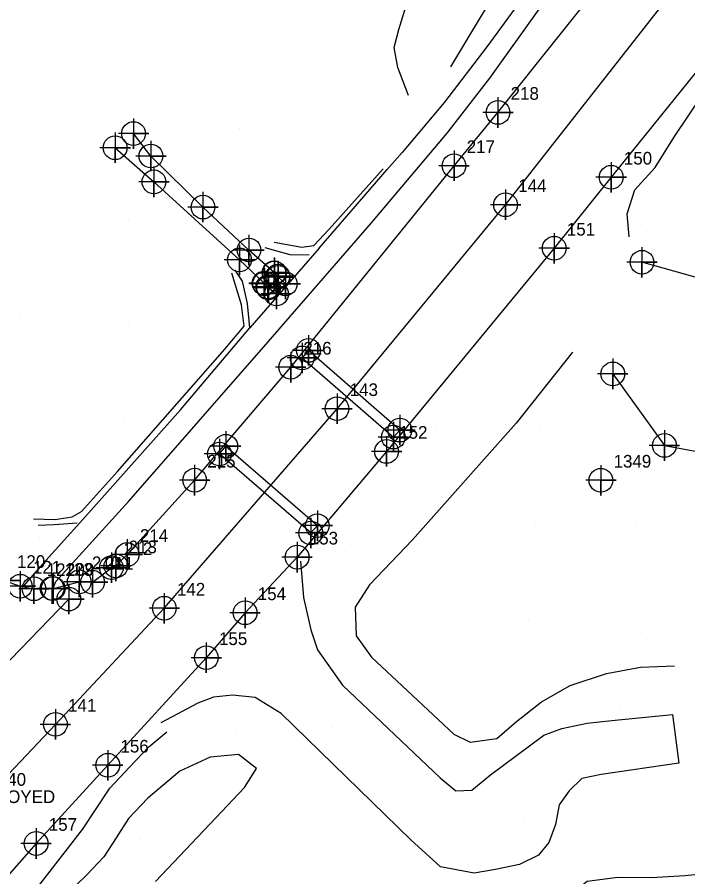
# Model space of a CAD drawing. Extents: x 1497074 to 1501343, y 481943 to 486114.
# Drawn here: x 1498585.8 to 1498718.1, y 484795.7 to 484965.4 of the extents above; entities that cross this region are included whole.
import ezdxf

# ---------------------------------------------------------------- set-up
doc = ezdxf.new("R2010")
doc.units = 0
for name, color, linetype in [('Default Symbol Cogo Comment', 7, 'Continuous'), ('Exist DTM Breakline', 7, 'Continuous'), ('Exist DTM Breakline Cogo Point CELL', 7, 'Continuous'), ('Exist DTM Crownline', 7, 'Continuous'), ('Exist DTM Crownline Cogo Number', 7, 'Continuous'), ('Exist DTM Crownline Cogo Point CELL', 7, 'Continuous'), ('Exist DTM Regular Point CELL', 7, 'Continuous'), ('Exist DTM Regular Point Cogo Number', 7, 'Continuous'), ('Exist Roads EOP', 7, 'Continuous'), ('Exist Roads EOP Cogo Number', 7, 'Continuous'), ('Exist Roads EOP Cogo Point CELL', 7, 'Continuous'), ('Exist Roads EOP Other', 7, 'Continuous'), ('Exist Roads EOP Other Cogo Point CELL', 7, 'Continuous'), ('PH Exist DTM Breakline', 7, 'Continuous'), ('PH Exist DTM Point', 7, 'Continuous'), ('Scratch_Level_8', 7, 'Continuous')]:
    doc.layers.add(name, color=color, linetype=linetype)

msp = doc.modelspace()

# ---------------------------------------------------------------- linework, layer by layer
at = {"layer": 'Exist DTM Breakline'}
for points in [[(1498808.2, 484833.18), (1498802.07, 484856.65), (1498795.16, 484873.78), (1498778.55, 484891.85), (1498758.28, 484902.66), (1498731.74, 484910.66), (1498709.09, 484916.99)], [(1498703.32, 484894.97), (1498713.52, 484880.84), (1498750.48, 484874.03), (1498781.67, 484873.31), (1498801.86, 484846.92)], [(1498566.89, 484820.13), (1498582.51, 484836.65), (1498595.96, 484850.53)]]:
    msp.add_lwpolyline(points, dxfattribs=at)
at = {"layer": 'Exist DTM Breakline Cogo Point CELL'}
for points in [[(1498709.09, 484919.99), (1498709.09, 484913.99), (1498709.09, 484916.99), (1498712.09, 484916.99), (1498706.09, 484916.99)], [(1498643.25, 484902.6), (1498643.25, 484896.6), (1498643.25, 484899.6), (1498646.25, 484899.6), (1498640.25, 484899.6)], [(1498642.03, 484901.11), (1498642.03, 484895.11), (1498642.03, 484898.11), (1498645.03, 484898.11), (1498639.03, 484898.11)], [(1498703.32, 484897.97), (1498703.32, 484891.97), (1498703.32, 484894.97), (1498706.32, 484894.97), (1498700.32, 484894.97)], [(1498661.31, 484886.87), (1498661.31, 484880.87), (1498661.31, 484883.87), (1498664.31, 484883.87), (1498658.31, 484883.87)], [(1498660.01, 484885.5), (1498660.01, 484879.5), (1498660.01, 484882.5), (1498663.01, 484882.5), (1498657.01, 484882.5)], [(1498626.94, 484883.68), (1498626.94, 484877.68), (1498626.94, 484880.68), (1498629.94, 484880.68), (1498623.94, 484880.68)], [(1498713.52, 484883.84), (1498713.52, 484877.84), (1498713.52, 484880.84), (1498716.52, 484880.84), (1498710.52, 484880.84)], [(1498625.69, 484882.16), (1498625.69, 484876.16), (1498625.69, 484879.16), (1498628.69, 484879.16), (1498622.69, 484879.16)], [(1498645.01, 484868.02), (1498645.01, 484862.02), (1498645.01, 484865.02), (1498648.01, 484865.02), (1498642.01, 484865.02)], [(1498643.72, 484866.57), (1498643.72, 484860.57), (1498643.72, 484863.57), (1498646.72, 484863.57), (1498640.72, 484863.57)], [(1498595.96, 484853.53), (1498595.96, 484847.53), (1498595.96, 484850.53), (1498598.96, 484850.53), (1498592.96, 484850.53)]]:
    msp.add_lwpolyline(points, dxfattribs=at)
for centre in [(1498709.09, 484916.99), (1498643.25, 484899.6), (1498642.03, 484898.11), (1498703.32, 484894.97), (1498660.01, 484882.5), (1498661.31, 484883.87), (1498626.94, 484880.68), (1498713.52, 484880.84), (1498625.69, 484879.16), (1498645.01, 484865.02), (1498643.72, 484863.57), (1498595.96, 484850.53)]:
    msp.add_circle(centre, 2.34, dxfattribs=at)
at = {"layer": 'Exist DTM Crownline'}
msp.add_lwpolyline([(1498174.51, 484418.76), (1498211.76, 484454.63), (1498248.88, 484490.3), (1498287.28, 484525.89), (1498324.11, 484560.63), (1498360.29, 484595.61), (1498397.16, 484630.83), (1498419.58, 484652.79), (1498435.06, 484667.86), (1498471.56, 484703.24), (1498507.82, 484739.07), (1498544.95, 484775.1), (1498579.44, 484811.19), (1498593.31, 484825.81), (1498614.8, 484848.72), (1498648.9, 484888.1), (1498682.16, 484928.34), (1498714.31, 484969.37), (1498734.43, 484994.62)], dxfattribs=at)
at = {"layer": 'Exist DTM Crownline Cogo Point CELL'}
for points in [[(1498682.16, 484931.34), (1498682.16, 484925.34), (1498682.16, 484928.34), (1498685.16, 484928.34), (1498679.16, 484928.34)], [(1498648.9, 484891.1), (1498648.9, 484885.1), (1498648.9, 484888.1), (1498651.9, 484888.1), (1498645.9, 484888.1)], [(1498614.8, 484851.72), (1498614.8, 484845.72), (1498614.8, 484848.72), (1498617.8, 484848.72), (1498611.8, 484848.72)], [(1498593.31, 484828.81), (1498593.31, 484822.81), (1498593.31, 484825.81), (1498596.31, 484825.81), (1498590.31, 484825.81)]]:
    msp.add_lwpolyline(points, dxfattribs=at)
for centre in [(1498682.16, 484928.34), (1498648.9, 484888.1), (1498614.8, 484848.72), (1498593.31, 484825.81)]:
    msp.add_circle(centre, 2.34, dxfattribs=at)
at = {"layer": 'Exist DTM Regular Point CELL'}
msp.add_lwpolyline([(1498700.98, 484876.97), (1498700.98, 484870.97), (1498700.98, 484873.97), (1498703.98, 484873.97), (1498697.98, 484873.97)], dxfattribs=at)
msp.add_circle((1498700.98, 484873.97), 2.34, dxfattribs=at)
at = {"layer": 'Exist Roads EOP'}
for points in [[(1498743.66, 484987.16), (1498738.5, 484978.99), (1498725.1, 484961.13), (1498703.01, 484933.77), (1498691.76, 484919.76), (1498658.67, 484879.66), (1498641.02, 484858.8), (1498630.75, 484847.82), (1498623.1, 484838.96), (1498603.65, 484817.74), (1498589.5, 484802.3), (1498575.55, 484786.5), (1498555.48, 484765.72), (1498538.21, 484747.04), (1498518.63, 484726.67), (1498501.9, 484709.28), (1498485.08, 484691.46), (1498474.43, 484677.64), (1498470.63, 484672.31)], [(1498592.65, 484852.62), (1498592.89, 484852.61), (1498598.02, 484853.93), (1498600.65, 484853.85), (1498604.36, 484856.72), (1498605.26, 484857.06), (1498607.49, 484859.32), (1498620.79, 484873.99), (1498639.75, 484896.28), (1498671.99, 484936.03), (1498680.66, 484946.55), (1498705.53, 484977.75)], [(1498496.38, 484929.75), (1498503.37, 484923.22), (1498504.49, 484924.34), (1498521.42, 484909.45), (1498521.11, 484906.86), (1498545.06, 484883.79), (1498566.71, 484864), (1498576.48, 484857.31), (1498583.22, 484854.18), (1498586.38, 484853.06), (1498589.08, 484852.56), (1498592.65, 484852.62)]]:
    msp.add_lwpolyline(points, dxfattribs=at)
at = {"layer": 'Exist Roads EOP Cogo Point CELL'}
for points in [[(1498680.66, 484949.55), (1498680.66, 484943.55), (1498680.66, 484946.55), (1498683.66, 484946.55), (1498677.66, 484946.55)], [(1498671.99, 484939.03), (1498671.99, 484933.03), (1498671.99, 484936.03), (1498674.99, 484936.03), (1498668.99, 484936.03)], [(1498703.01, 484936.77), (1498703.01, 484930.77), (1498703.01, 484933.77), (1498706.01, 484933.77), (1498700.01, 484933.77)], [(1498691.76, 484922.76), (1498691.76, 484916.76), (1498691.76, 484919.76), (1498694.76, 484919.76), (1498688.76, 484919.76)], [(1498639.75, 484899.28), (1498639.75, 484893.28), (1498639.75, 484896.28), (1498642.75, 484896.28), (1498636.75, 484896.28)], [(1498658.67, 484882.66), (1498658.67, 484876.66), (1498658.67, 484879.66), (1498661.67, 484879.66), (1498655.67, 484879.66)], [(1498620.79, 484876.99), (1498620.79, 484870.99), (1498620.79, 484873.99), (1498623.79, 484873.99), (1498617.79, 484873.99)], [(1498607.49, 484862.32), (1498607.49, 484856.32), (1498607.49, 484859.32), (1498610.49, 484859.32), (1498604.49, 484859.32)], [(1498641.02, 484861.8), (1498641.02, 484855.8), (1498641.02, 484858.8), (1498644.02, 484858.8), (1498638.02, 484858.8)], [(1498604.36, 484859.72), (1498604.36, 484853.72), (1498604.36, 484856.72), (1498607.36, 484856.72), (1498601.36, 484856.72)], [(1498605.26, 484860.06), (1498605.26, 484854.06), (1498605.26, 484857.06), (1498608.26, 484857.06), (1498602.26, 484857.06)], [(1498583.22, 484857.18), (1498583.22, 484851.18), (1498583.22, 484854.18), (1498586.22, 484854.18), (1498580.22, 484854.18)], [(1498586.38, 484856.06), (1498586.38, 484850.06), (1498586.38, 484853.06), (1498589.38, 484853.06), (1498583.38, 484853.06)], [(1498598.02, 484856.93), (1498598.02, 484850.93), (1498598.02, 484853.93), (1498601.02, 484853.93), (1498595.02, 484853.93)], [(1498600.65, 484856.85), (1498600.65, 484850.85), (1498600.65, 484853.85), (1498603.65, 484853.85), (1498597.65, 484853.85)], [(1498589.08, 484855.56), (1498589.08, 484849.56), (1498589.08, 484852.56), (1498592.08, 484852.56), (1498586.08, 484852.56)], [(1498592.65, 484855.62), (1498592.65, 484849.62), (1498592.65, 484852.62), (1498595.65, 484852.62), (1498589.65, 484852.62)], [(1498592.89, 484855.61), (1498592.89, 484849.61), (1498592.89, 484852.61), (1498595.89, 484852.61), (1498589.89, 484852.61)], [(1498630.75, 484850.82), (1498630.75, 484844.82), (1498630.75, 484847.82), (1498633.75, 484847.82), (1498627.75, 484847.82)], [(1498623.1, 484841.96), (1498623.1, 484835.96), (1498623.1, 484838.96), (1498626.1, 484838.96), (1498620.1, 484838.96)], [(1498603.65, 484820.74), (1498603.65, 484814.74), (1498603.65, 484817.74), (1498606.65, 484817.74), (1498600.65, 484817.74)], [(1498589.5, 484805.3), (1498589.5, 484799.3), (1498589.5, 484802.3), (1498592.5, 484802.3), (1498586.5, 484802.3)]]:
    msp.add_lwpolyline(points, dxfattribs=at)
for centre in [(1498680.66, 484946.55), (1498671.99, 484936.03), (1498703.01, 484933.77), (1498691.76, 484919.76), (1498639.75, 484896.28), (1498658.67, 484879.66), (1498620.79, 484873.99), (1498607.49, 484859.32), (1498641.02, 484858.8), (1498605.26, 484857.06), (1498604.36, 484856.72), (1498598.02, 484853.93), (1498600.65, 484853.85), (1498586.38, 484853.06), (1498589.08, 484852.56), (1498592.65, 484852.62), (1498592.89, 484852.61), (1498630.75, 484847.82), (1498623.1, 484838.96), (1498603.65, 484817.74), (1498589.5, 484802.3)]:
    msp.add_circle(centre, 2.34, dxfattribs=at)
at = {"layer": 'Exist Roads EOP Other'}
for points in [[(1498638.7, 484912.74), (1498637.27, 484914.02), (1498637.22, 484914.25), (1498636.53, 484914.87), (1498636.46, 484914.94), (1498631.52, 484919.41), (1498622.44, 484927.88), (1498612.16, 484937.96), (1498608.74, 484942.39)], [(1498605.1, 484939.58), (1498612.76, 484932.86), (1498629.64, 484917.46), (1498634.51, 484912.88), (1498634.6, 484912.75), (1498635.25, 484912.13), (1498635.39, 484911.94), (1498636.94, 484910.73)]]:
    msp.add_lwpolyline(points, dxfattribs=at)
at = {"layer": 'Exist Roads EOP Other Cogo Point CELL'}
for points in [[(1498608.74, 484945.39), (1498608.74, 484939.39), (1498608.74, 484942.39), (1498611.74, 484942.39), (1498605.74, 484942.39)], [(1498605.1, 484942.58), (1498605.1, 484936.58), (1498605.1, 484939.58), (1498608.1, 484939.58), (1498602.1, 484939.58)], [(1498612.16, 484940.96), (1498612.16, 484934.96), (1498612.16, 484937.96), (1498615.16, 484937.96), (1498609.16, 484937.96)], [(1498612.76, 484935.86), (1498612.76, 484929.86), (1498612.76, 484932.86), (1498615.76, 484932.86), (1498609.76, 484932.86)], [(1498622.44, 484930.88), (1498622.44, 484924.88), (1498622.44, 484927.88), (1498625.44, 484927.88), (1498619.44, 484927.88)], [(1498631.52, 484922.41), (1498631.52, 484916.41), (1498631.52, 484919.41), (1498634.52, 484919.41), (1498628.52, 484919.41)], [(1498629.64, 484920.46), (1498629.64, 484914.46), (1498629.64, 484917.46), (1498632.64, 484917.46), (1498626.64, 484917.46)], [(1498636.46, 484917.94), (1498636.46, 484911.94), (1498636.46, 484914.94), (1498639.46, 484914.94), (1498633.46, 484914.94)], [(1498636.53, 484917.87), (1498636.53, 484911.87), (1498636.53, 484914.87), (1498639.53, 484914.87), (1498633.53, 484914.87)], [(1498637.22, 484917.25), (1498637.22, 484911.25), (1498637.22, 484914.25), (1498640.22, 484914.25), (1498634.22, 484914.25)], [(1498637.27, 484917.02), (1498637.27, 484911.02), (1498637.27, 484914.02), (1498640.27, 484914.02), (1498634.27, 484914.02)], [(1498634.51, 484915.88), (1498634.51, 484909.88), (1498634.51, 484912.88), (1498637.51, 484912.88), (1498631.51, 484912.88)], [(1498634.6, 484915.75), (1498634.6, 484909.75), (1498634.6, 484912.75), (1498637.6, 484912.75), (1498631.6, 484912.75)], [(1498638.7, 484915.74), (1498638.7, 484909.74), (1498638.7, 484912.74), (1498641.7, 484912.74), (1498635.7, 484912.74)], [(1498635.25, 484915.13), (1498635.25, 484909.13), (1498635.25, 484912.13), (1498638.25, 484912.13), (1498632.25, 484912.13)], [(1498635.39, 484914.94), (1498635.39, 484908.94), (1498635.39, 484911.94), (1498638.39, 484911.94), (1498632.39, 484911.94)], [(1498636.94, 484913.73), (1498636.94, 484907.73), (1498636.94, 484910.73), (1498639.94, 484910.73), (1498633.94, 484910.73)]]:
    msp.add_lwpolyline(points, dxfattribs=at)
for centre in [(1498608.74, 484942.39), (1498605.1, 484939.58), (1498612.16, 484937.96), (1498612.76, 484932.86), (1498622.44, 484927.88), (1498631.52, 484919.41), (1498629.64, 484917.46), (1498636.46, 484914.94), (1498636.53, 484914.87), (1498634.51, 484912.88), (1498637.22, 484914.25), (1498637.27, 484914.02), (1498634.6, 484912.75), (1498635.25, 484912.13), (1498635.39, 484911.94), (1498638.7, 484912.74), (1498636.94, 484910.73)]:
    msp.add_circle(centre, 2.34, dxfattribs=at)
at = {"layer": 'PH Exist DTM Breakline'}
for p, q in [((1498647.32, 484923.52), (1498658, 484935.46)), ((1498644.29, 484920.28), (1498647.32, 484923.52)), ((1498636.5, 484920.97), (1498641.92, 484919.99)), ((1498641.92, 484919.99), (1498644.29, 484920.28)), ((1498630.05, 484908.6), (1498628.12, 484914.81)), ((1498630.6, 484904.35), (1498630.05, 484908.6)), ((1498626.76, 484899.83), (1498630.6, 484904.35)), ((1498605.56, 484875.72), (1498626.76, 484899.83)), ((1498598.47, 484867.79), (1498605.56, 484875.72)), ((1498596.61, 484866.79), (1498598.47, 484867.79)), ((1498588.98, 484866.33), (1498593.18, 484866.22)), ((1498593.18, 484866.22), (1498596.61, 484866.79))]:
    msp.add_line(p, q, dxfattribs=at)
for points in [[(1498707.33, 485006.81), (1498705.58, 485003.73), (1498702.48, 484996.73), (1498699.07, 484990.75), (1498691.28, 484977.76), (1498684.77, 484968.13), (1498678.44, 484959.51), (1498670.09, 484948.6), (1498661.74, 484938.65), (1498658.81, 484935.28)], [(1498663.02, 484949.92), (1498660.89, 484955.44), (1498660.18, 484959.35), (1498661.07, 484962.93), (1498662.41, 484967.19), (1498664.29, 484971.46), (1498666.63, 484976.54), (1498669.65, 484982.28), (1498672.11, 484987.03), (1498674.23, 484991.87), (1498675.21, 484998.46), (1498676.62, 485002.54), (1498678.02, 485005.86)], [(1498592.95, 484852.78), (1498593.42, 484854.02), (1498607.82, 484869.88), (1498635.31, 484901.31), (1498655.7, 484924.76), (1498670.64, 484942.46), (1498679.07, 484953.32), (1498688.77, 484966.91), (1498701.36, 484986.63), (1498705.52, 484994.13), (1498710.78, 485004.48)], [(1498671.33, 484955.56), (1498680.56, 484970.97), (1498681.88, 484977.99), (1498682.41, 484983.76), (1498683.54, 484988.21), (1498685.71, 484992.14), (1498689.37, 484996.25), (1498693.6, 485000.49), (1498697.94, 485003.38)], [(1498706.55, 484921.99), (1498706.13, 484926.58), (1498707.65, 484931.3), (1498711.69, 484935.67), (1498715.53, 484941.78), (1498720.92, 484949.82), (1498726.19, 484955.72), (1498730.85, 484960.76), (1498734.77, 484964.84), (1498739.7, 484965.86), (1498744.51, 484966.09), (1498746.01, 484969.02), (1498747.51, 484974.22), (1498748.06, 484978.13), (1498747.78, 484981.24)], [(1498645.35, 484919.79), (1498658.81, 484935.28)], [(1498645.35, 484919.79), (1498631.69, 484904.08)], [(1498634.63, 484919.92), (1498639.56, 484918.5), (1498643.41, 484918.49)], [(1498631.69, 484904.08), (1498631.21, 484908.83), (1498630.21, 484913.26), (1498628.81, 484915.4)], [(1498598.75, 484866.22), (1498618.03, 484887.87), (1498631.69, 484904.08)], [(1498695.35, 484899.27), (1498684.24, 484885.27), (1498663.79, 484862.23), (1498655.32, 484853.32), (1498652.48, 484848.93), (1498652.7, 484843.3), (1498655.73, 484839.07), (1498661.72, 484833.39), (1498671.97, 484823.85), (1498675.16, 484822.29), (1498680.45, 484823.01), (1498684.35, 484826.38), (1498689.26, 484830.24), (1498694.89, 484833.48), (1498702.07, 484835.83), (1498708.78, 484837.09), (1498715.5, 484837.37)], [(1498598.75, 484866.22), (1498590.85, 484857.46), (1498586.96, 484853.08)], [(1498589.88, 484865.1), (1498593.08, 484865.24), (1498597.59, 484865.59)], [(1498641.66, 484858), (1498642.27, 484850.83), (1498643.73, 484844.46), (1498645.02, 484840.49), (1498650, 484833.55), (1498669.26, 484815.26), (1498672.33, 484812.72), (1498675.51, 484812.82), (1498679.16, 484815.85), (1498689.74, 484823.7), (1498693.3, 484824.97), (1498698.28, 484826.02), (1498703.16, 484826.59), (1498715.12, 484827.74), (1498716.35, 484818.16), (1498701.01, 484815.9), (1498697.21, 484815.12), (1498694.71, 484812.7), (1498692.75, 484809.92), (1498691.99, 484806.06), (1498690.67, 484802.47), (1498688.65, 484800.02), (1498684.91, 484798.17), (1498680.16, 484797.19), (1498675.95, 484796.45), (1498669.29, 484797.71), (1498663.44, 484803.04), (1498637.84, 484827.97), (1498632.73, 484831.08), (1498628.29, 484831.56), (1498624.51, 484831.14), (1498621.41, 484830.02), (1498614.09, 484826.14)], [(1498587.48, 484790.67), (1498598.66, 484805.04), (1498604.04, 484813.23), (1498607.95, 484817.39), (1498611.76, 484821.39), (1498615.32, 484824.33)], [(1498613.04, 484794.82), (1498618.97, 484801.06), (1498624.95, 484807.35), (1498630.64, 484813.35), (1498632.97, 484817.1), (1498629.42, 484819.88), (1498623.87, 484819.36), (1498617.86, 484816.6), (1498611.57, 484811.27), (1498607.72, 484807.21), (1498605.28, 484803.4), (1498602.9, 484799.65), (1498599.54, 484796.11), (1498595.29, 484792.03)], [(1498763.56, 484794.31), (1498744.83, 484796.11), (1498738.07, 484796.71), (1498731.78, 484797.17), (1498724.97, 484796.7), (1498717.62, 484795.94), (1498710.92, 484795.54), (1498704.32, 484795.61), (1498698.28, 484794.78), (1498694.33, 484791.72), (1498692.02, 484789.28), (1498685.41, 484785.03), (1498678.23, 484782.05), (1498671.57, 484779.37), (1498664.71, 484774.06), (1498660.11, 484769.43), (1498655.29, 484764.35), (1498651.54, 484760.4), (1498646.8, 484755.42), (1498641.81, 484751.48), (1498635.97, 484749.35), (1498631.53, 484748.05)]]:
    msp.add_lwpolyline(points, dxfattribs=at)
at = {"layer": 'PH Exist DTM Point'}
for p, q in [((1498629.38, 484963.67), (1498629.38, 484963.67)), ((1498649.88, 484963.19), (1498649.88, 484963.19)), ((1498668.78, 484964.18), (1498668.78, 484964.18)), ((1498665.55, 484947.12), (1498665.55, 484947.12)), ((1498648.48, 484944.52), (1498648.48, 484944.52)), ((1498610.67, 484942.44), (1498610.67, 484942.44)), ((1498629.71, 484943.35), (1498629.71, 484943.35)), ((1498646.55, 484926.36), (1498646.55, 484926.36)), ((1498607.81, 484925.16), (1498607.81, 484925.16)), ((1498628.06, 484924.92), (1498628.06, 484924.92)), ((1498708.9, 484924.37), (1498708.9, 484924.37)), ((1498586.18, 484906.71), (1498586.18, 484906.71)), ((1498607.81, 484905.16), (1498607.81, 484905.16)), ((1498627.17, 484904.48), (1498627.17, 484904.48)), ((1498691.77, 484901.83), (1498691.77, 484901.83)), ((1498588.32, 484884.68), (1498588.32, 484884.68)), ((1498606.98, 484885.95), (1498606.98, 484885.95)), ((1498626.95, 484885.97), (1498626.95, 484885.97)), ((1498668.38, 484884.62), (1498668.38, 484884.62)), ((1498689.01, 484884.03), (1498689.01, 484884.03)), ((1498609.66, 484866.19), (1498609.66, 484866.19)), ((1498688.1, 484864.95), (1498688.1, 484864.95)), ((1498708.01, 484864.97), (1498708.01, 484864.97)), ((1498590.25, 484862.73), (1498590.25, 484862.73)), ((1498669.67, 484863.34), (1498669.67, 484863.34)), ((1498651.65, 484861.23), (1498651.65, 484861.23)), ((1498649.1, 484849.15), (1498649.1, 484849.15)), ((1498686.69, 484846.28), (1498686.69, 484846.28)), ((1498668.75, 484844.27), (1498668.75, 484844.27)), ((1498709, 484844.03), (1498709, 484844.03)), ((1498682.1, 484830.67), (1498682.1, 484830.67)), ((1498704.79, 484829.36), (1498704.79, 484829.36)), ((1498672.91, 484827.51), (1498672.91, 484827.51)), ((1498629.06, 484823.92), (1498629.06, 484823.92)), ((1498647.85, 484825.2), (1498647.85, 484825.2)), ((1498705.26, 484810.04), (1498705.26, 484810.04)), ((1498624.19, 484808.6), (1498624.19, 484808.6)), ((1498685.79, 484807.08), (1498685.79, 484807.08)), ((1498653.12, 484804.08), (1498653.12, 484804.08)), ((1498609.91, 484803.16), (1498609.91, 484803.16))]:
    msp.add_line(p, q, dxfattribs=at)
at = {"layer": 'Scratch_Level_8'}
for points in [[(1498660.01, 484882.5), (1498661.31, 484883.87), (1498643.25, 484899.6), (1498642.03, 484898.11), (1498660.01, 484882.5)], [(1498625.69, 484879.16), (1498626.94, 484880.68), (1498645.01, 484865.02), (1498643.72, 484863.57), (1498625.69, 484879.16)]]:
    msp.add_lwpolyline(points, dxfattribs=at)

# ---------------------------------------------------------------- texts
at = {"layer": 'Default Symbol Cogo Comment'}
msp.add_text('B5243-2 DESTROYED', height=2.5, dxfattribs=at).set_placement((1498558.89, 484810.28))
at = {"layer": 'Exist DTM Crownline Cogo Number'}
for s, p in [('144', (1498684.66, 484930.84)), ('143', (1498651.4, 484890.6)), ('142', (1498617.3, 484851.22)), ('141', (1498595.81, 484828.31)), ('140', (1498581.94, 484813.69))]:
    msp.add_text(s, height=2.5, dxfattribs=at).set_placement(p)
at = {"layer": 'Exist DTM Regular Point Cogo Number'}
msp.add_text('1349', height=2.5, dxfattribs=at).set_placement((1498703.48, 484876.47))
at = {"layer": 'Exist Roads EOP Cogo Number'}
for s, p in [('218', (1498683.16, 484949.05)), ('217', (1498674.49, 484938.53)), ('150', (1498705.51, 484936.27)), ('151', (1498694.26, 484922.26)), ('216', (1498642.25, 484898.78)), ('152', (1498661.17, 484882.17)), ('215', (1498623.29, 484876.49)), ('214', (1498609.99, 484861.82)), ('153', (1498643.52, 484861.3)), ('212', (1498606.86, 484859.22)), ('213', (1498607.76, 484859.57)), ('120', (1498585.72, 484856.68)), ('121', (1498588.88, 484855.56)), ('122', (1498591.58, 484855.06)), ('123', (1498595.15, 484855.12)), ('209', (1498595.39, 484855.11)), ('210', (1498600.52, 484856.43)), ('211', (1498603.15, 484856.35)), ('154', (1498633.25, 484850.32)), ('155', (1498625.6, 484841.46)), ('156', (1498606.15, 484820.24)), ('157', (1498592, 484804.8))]:
    msp.add_text(s, height=2.5, dxfattribs=at).set_placement(p)

doc.saveas('drawing.dxf')
